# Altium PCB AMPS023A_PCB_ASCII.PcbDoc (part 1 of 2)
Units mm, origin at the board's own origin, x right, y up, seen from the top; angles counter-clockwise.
Board outline 85 x 120 mm, 4 copper layers (Top Layer, Signal Layer 1, Signal Layer 2, Bottom Layer), stack 1.567 mm thick; 131 components, 63 nets, 410 pads, 509 vias.
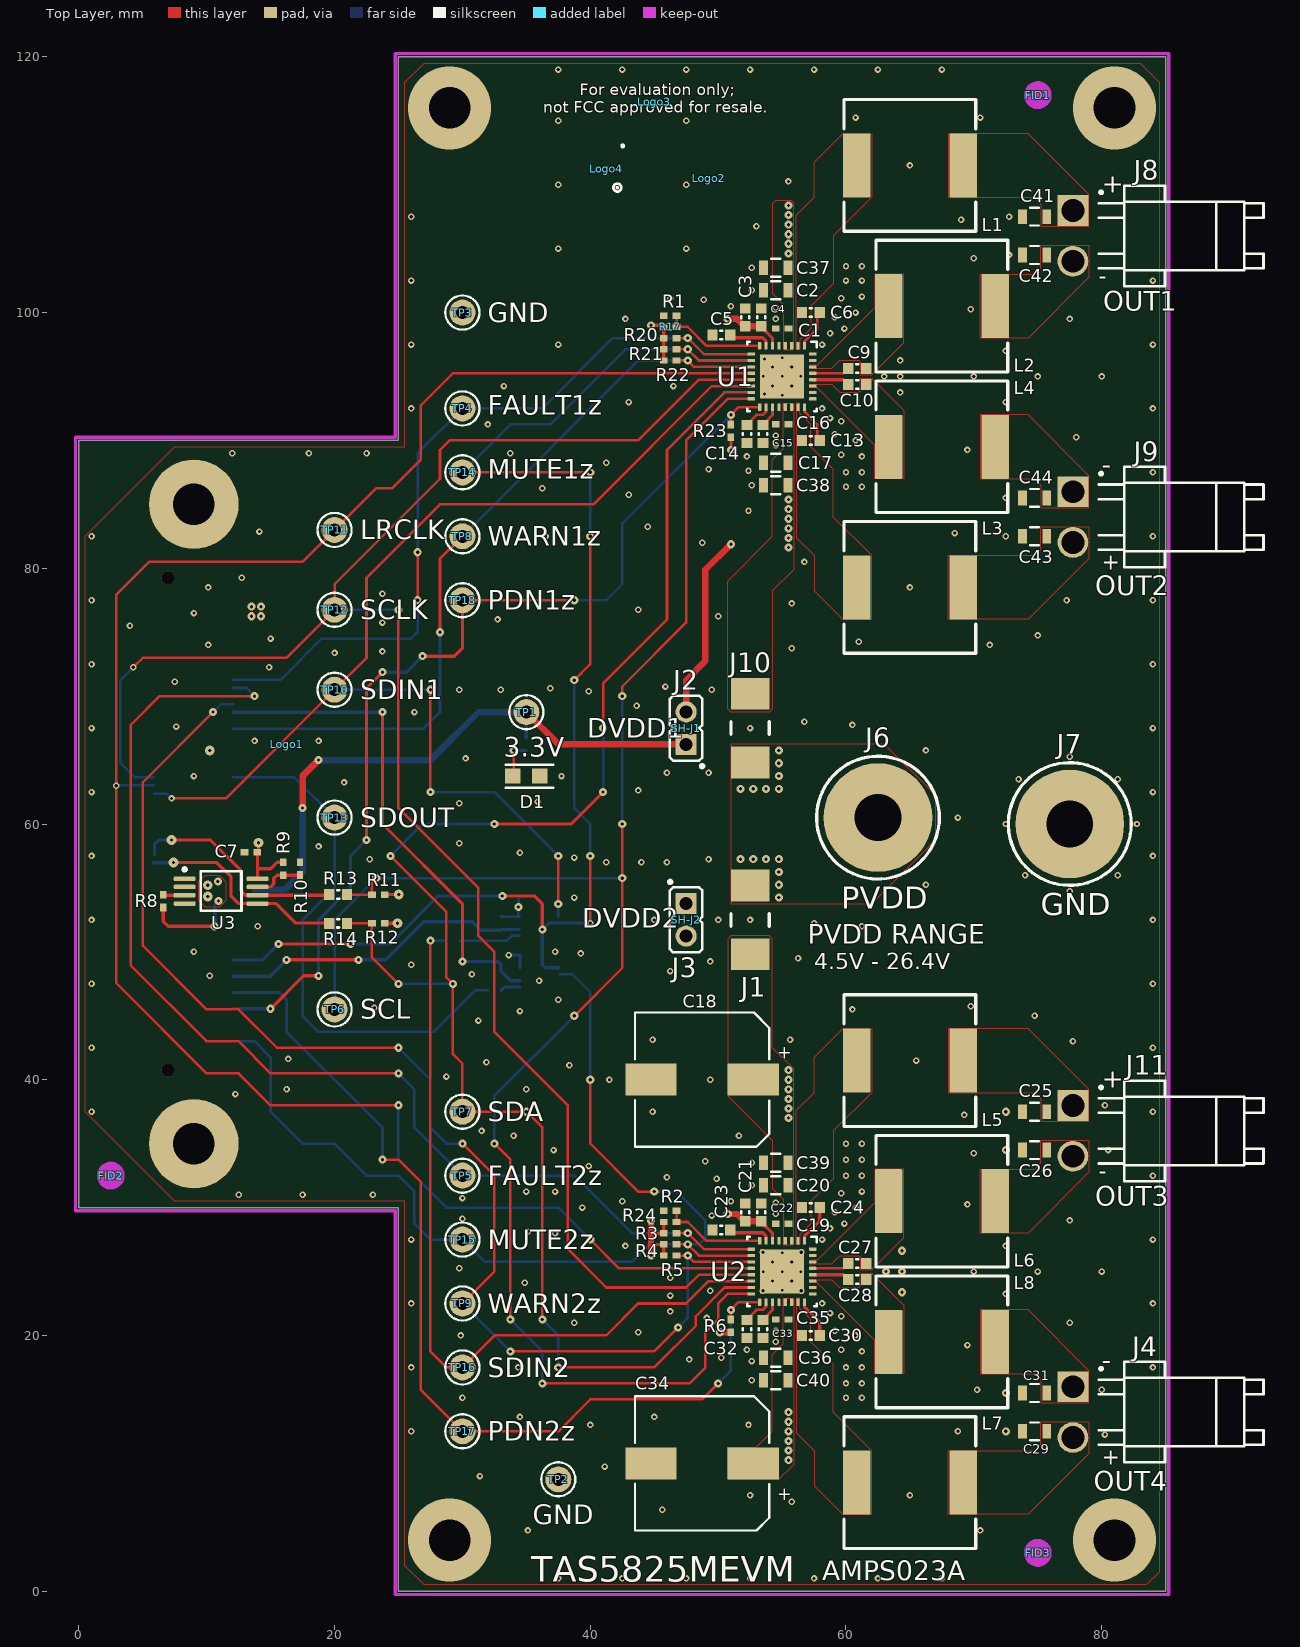
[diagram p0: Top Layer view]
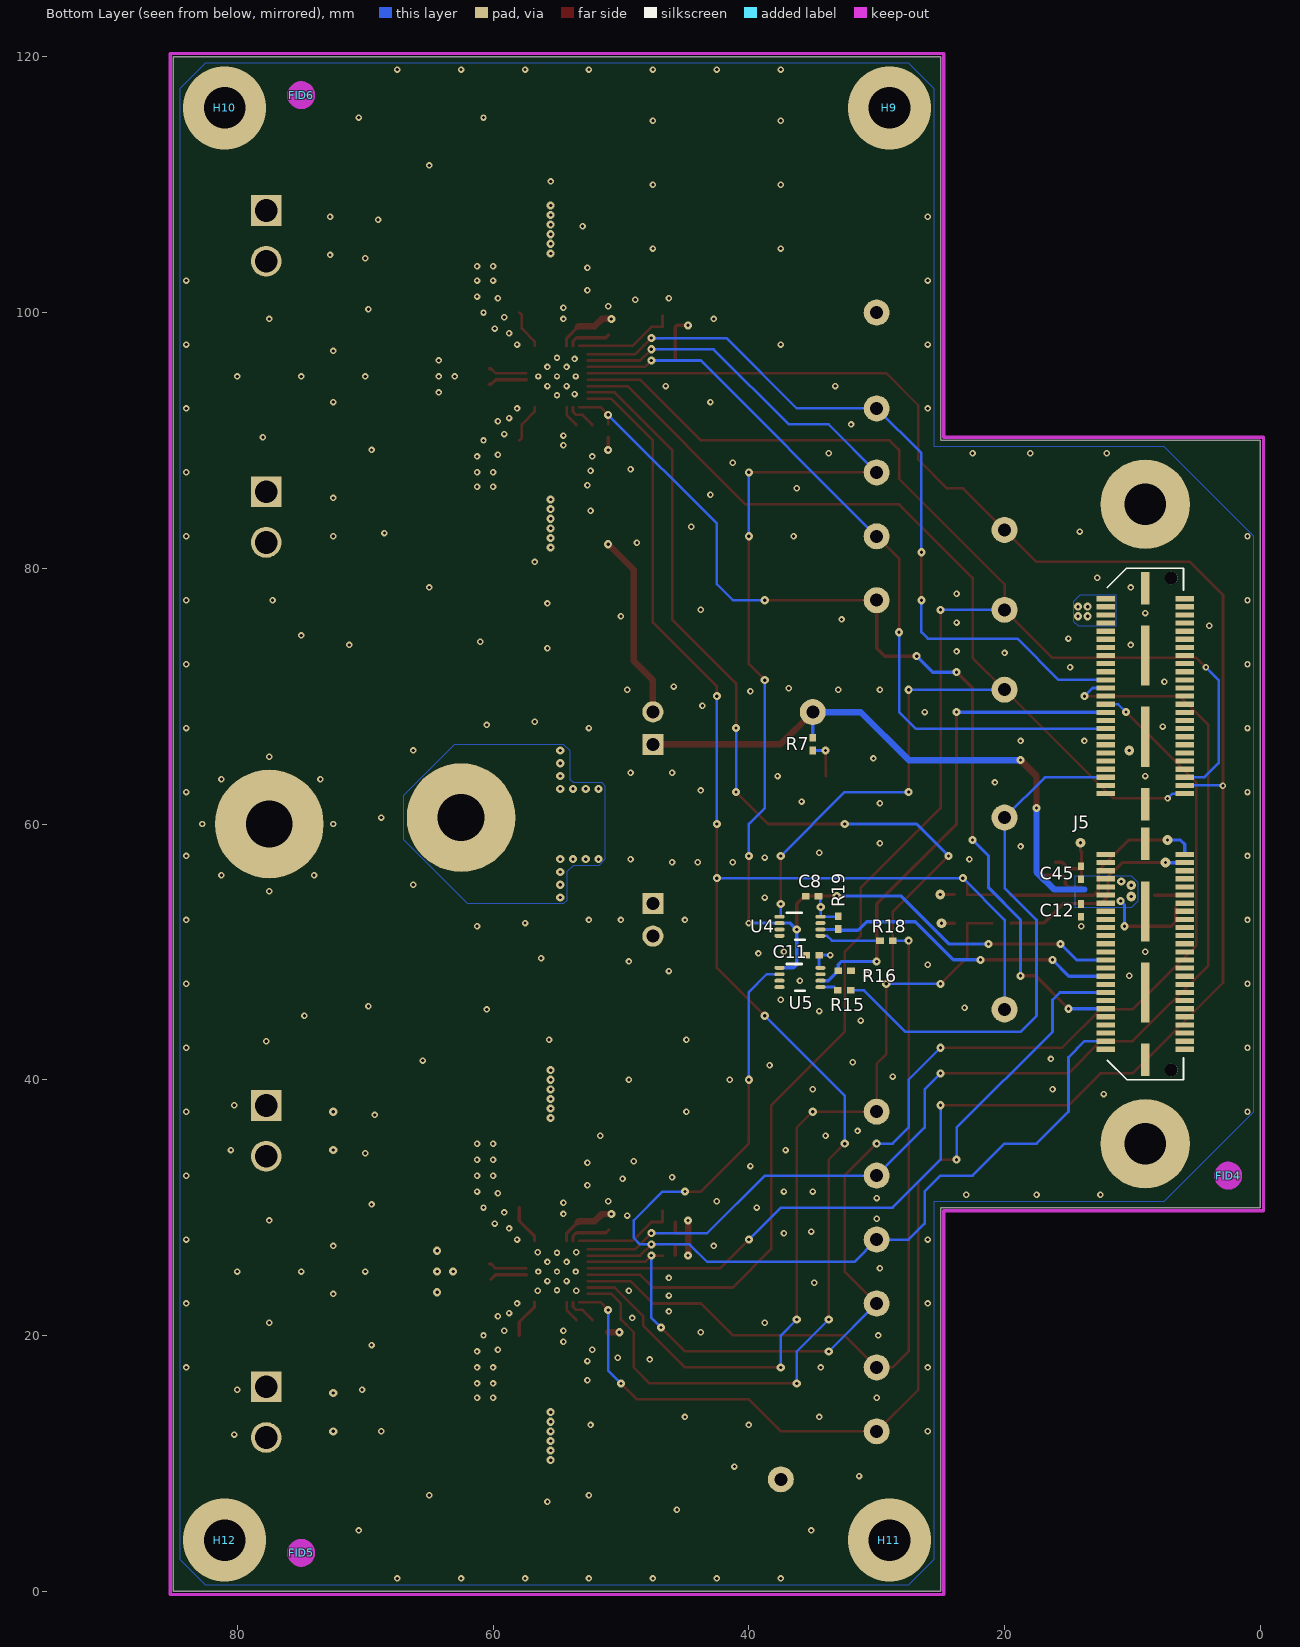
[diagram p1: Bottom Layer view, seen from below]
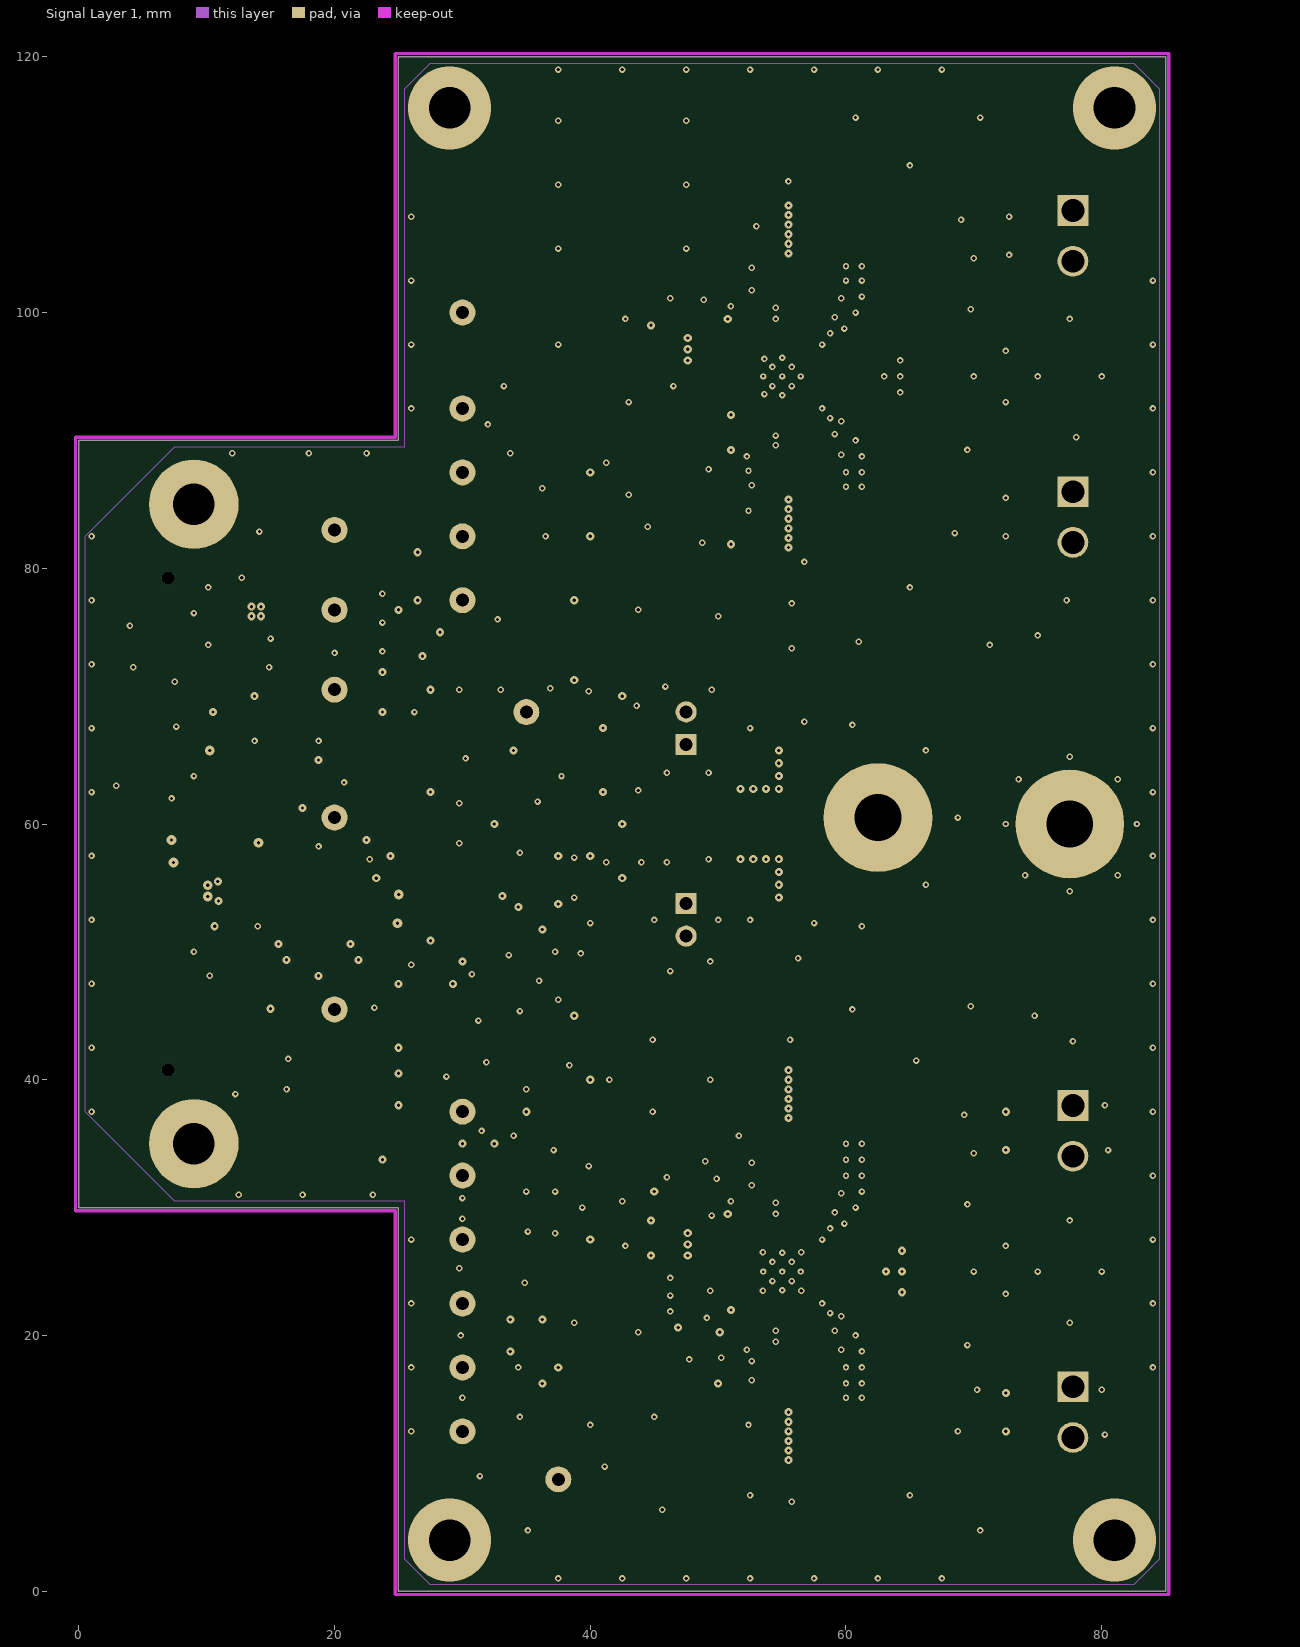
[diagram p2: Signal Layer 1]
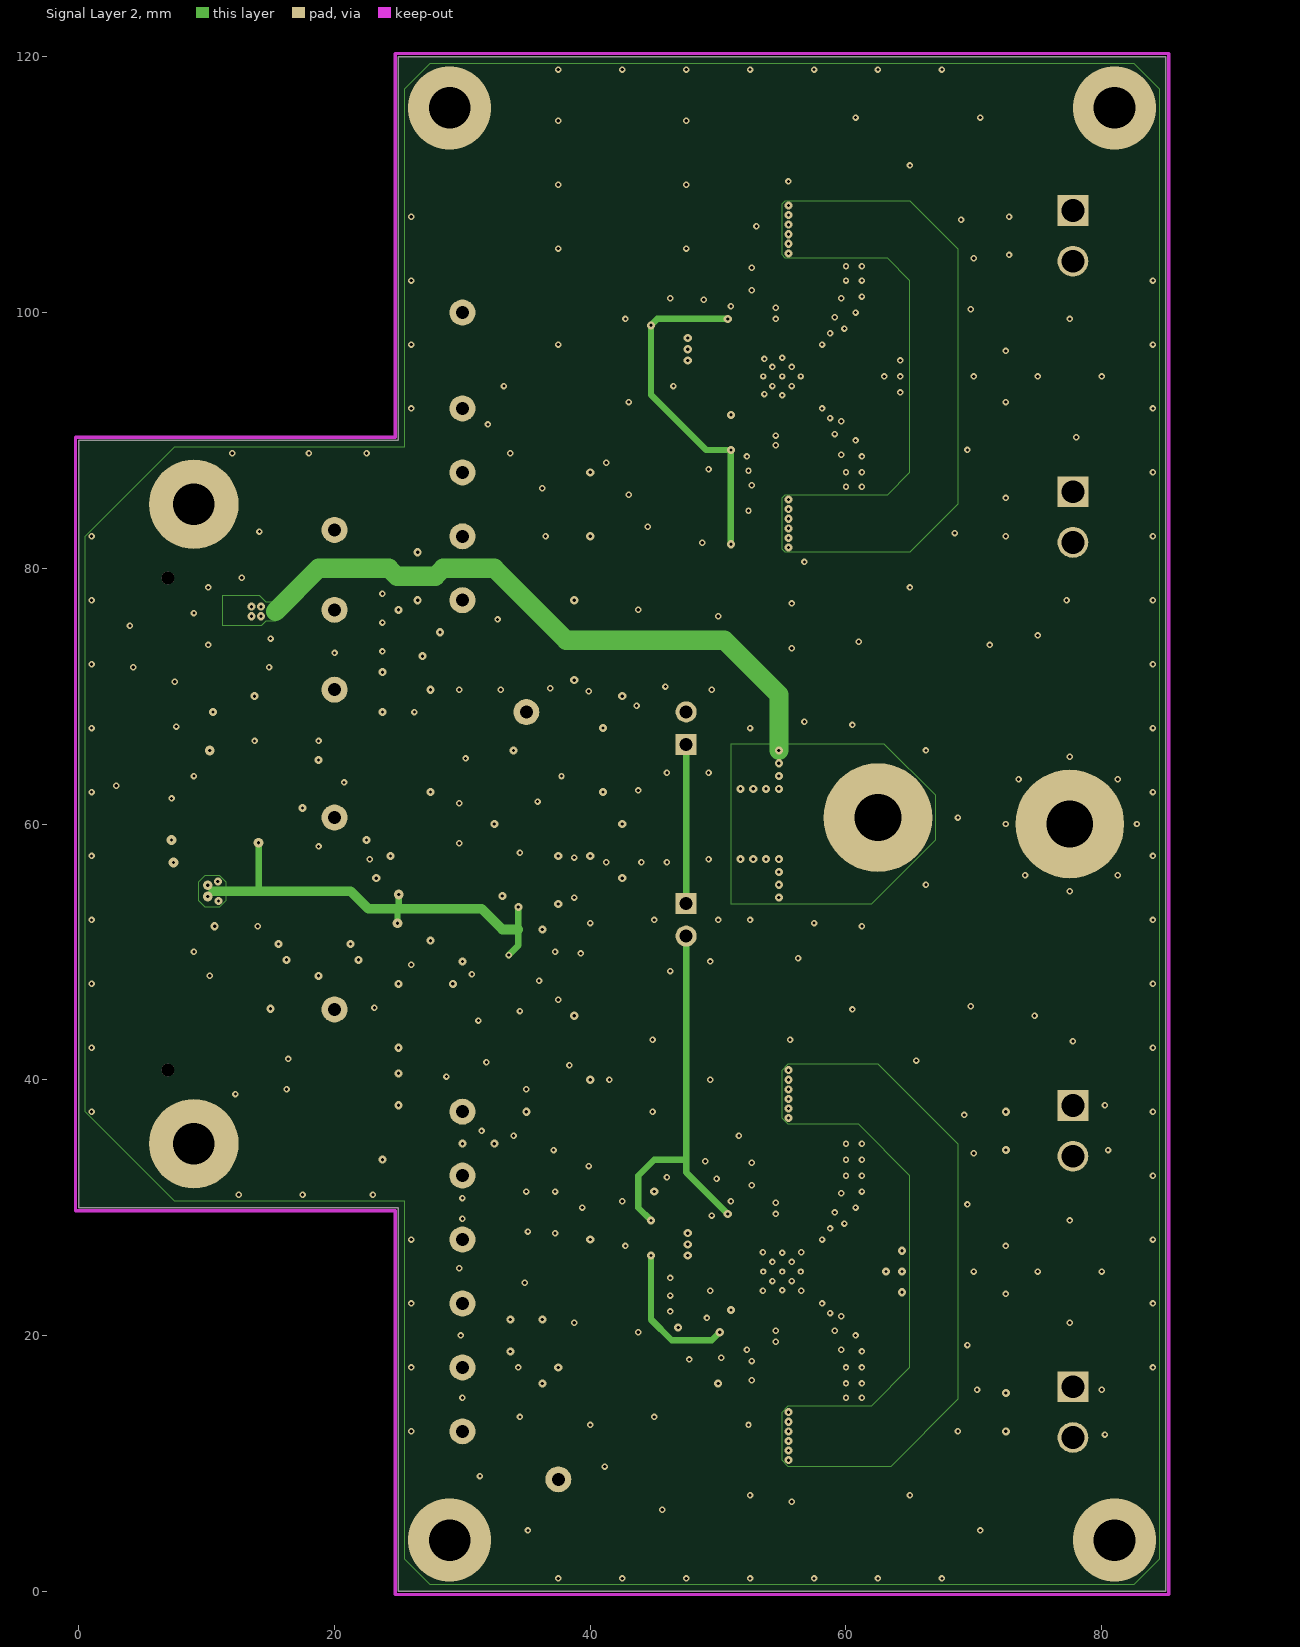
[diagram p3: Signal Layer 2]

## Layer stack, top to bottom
Top Solder: solder mask 0.0102, Solder Resist, Dk 3.5
Top Layer: signal copper 0.0696
Dielectric 1: prepreg 0.2032, FR-4, Dk 4.2
Signal Layer 1: signal copper 0.0356
Dielectric 2: core 0.9505, FR-4, Dk 4.2
Signal Layer 2: signal copper 0.0356
Dielectric 3: prepreg 0.2032, FR-4, Dk 4.2
Bottom Layer: signal copper 0.0696
Bottom Solder: solder mask 0.0102, Solder Resist, Dk 3.5

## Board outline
0,30 25,30 25,0 85,0 85,120 25,120 25,90 0,90

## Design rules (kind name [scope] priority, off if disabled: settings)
AcuteAngle [All] p0: scope1count=1 scope1_0_kind=Board scope1_0_value=Board scope2count=1 scope2_0_kind=Board scope2_0_value=Board commentlength=0 minimum=4.50000000000000E+0001
AcuteAngle [All] p1: minimum=4.50000000000000E+0001 checktracksonly=FALSE
AssemblyTestPointUsage [All] p0: scope1count=1 scope1_0_kind=Board scope1_0_value=Board scope2count=1 scope2_0_kind=Board scope2_0_value=Board commentlength=0
AssemblyTestPointUsage [All] p1: valid=2
AssemblyTestpoint [All] p0: scope1count=1 scope1_0_kind=Board scope1_0_value=Board scope2count=1 scope2_0_kind=Board scope2_0_value=Board commentlength=0
Clearance [All] p0: scope1count=1 scope1_0_kind=Board scope1_0_value=Board scope2count=1 scope2_0_kind=Board scope2_0_value=Board commentlength=0 gap=0.2
Clearance Clearance_Poly [All] p0 off: scope1count=1 scope1_0_kind=Board scope1_0_value=Board scope2count=1 scope2_0_kind=Board scope2_0_value=Board commentlength=48 gap=0.25 // Protel DXP Scope 1 Expression Was: InPolygon
Clearance Clearance_Keepouts [All] p0 off: scope1count=1 scope1_0_kind=Board scope1_0_value=Board scope2count=1 scope2_0_kind=Board scope2_0_value=Board commentlength=99 gap=0 // Protel DXP Scope 2 Expression Was: ((IsTrack Or IsArc) And Not InPoly) And IsFree and IsKeepOut
Clearance "Poly Clearance PVDD" [All] p0: scope1count=1 scope1_0_kind=Board scope1_0_value=Board scope2count=1 scope2_0_kind=Board scope2_0_value=Board commentlength=0 gap=0.2
Clearance "Poly Clearance Outputs" [All] p0 off: scope1count=1 scope1_0_kind=Board scope1_0_value=Board scope2count=1 scope2_0_kind=Board scope2_0_value=Board commentlength=82 gap=0.2 // Protel DXP Scope 2 Expression Was: (InComponent('UD1') AND InComponent('UD2'))
Clearance "Poly Clearance 3.3V" [All] p0 off: scope1count=1 scope1_0_kind=Board scope1_0_value=Board scope2count=1 scope2_0_kind=Board scope2_0_value=Board commentlength=71 gap=0.2 // Protel DXP Scope 1 Expression Was: InNamedPolygon('+3.3V_L04_P006')
Clearance Clearance_BoardEdge_MountingHoles [All] p0 off: scope1count=1 scope1_0_kind=Board scope1_0_value=Board scope2count=1 scope2_0_kind=Board scope2_0_value=Board commentlength=48 gap=0.2 // Protel DXP Scope 2 Expression Was: IsKeepOut
Clearance Clearance_BoardEdge_Poly [All] p0 off: scope1count=1 scope1_0_kind=Board scope1_0_value=Board scope2count=1 scope2_0_kind=Board scope2_0_value=Board commentlength=48 gap=0.2 // Protel DXP Scope 2 Expression Was: IsKeepOut
Clearance Clearance_BoardEdge [All] p0 off: scope1count=1 scope1_0_kind=Board scope1_0_value=Board scope2count=1 scope2_0_kind=Board scope2_0_value=Board commentlength=48 gap=0.2 // Protel DXP Scope 2 Expression Was: IsKeepOut
Clearance "Clearance Fiducial LibErrors" [All] p0: scope1count=1 scope1_0_kind=Component scope1_0_value=FID* scope2count=1 scope2_0_kind=Board scope2_0_value=Board commentlength=0 gap=0.2
Clearance "Clearance Fiducial LibErrors" [InComponent('FID*')] p1: gap=0.2 ignorepadtopadclearanceinfootprint=TRUE except(0: Arc-SMDPad Arc-Hole Track-SMDPad Track-Hole SMDPad-Hole THPad-Hole Via-Hole Fill-Hole Poly-Hole Region-Hole Text-Hole)
Clearance Clearance_BoardEdge [OnCopper and Not InComponentClass('Logo') and not InComponentClass('FiducialMark') and not InRegion(1000,500,4000,800) and Not IsKeepout vs IsKeepOut] p2: gap=0.2 ignorepadtopadclearanceinfootprint=FALSE except(0: Arc-Hole Track-Hole SMDPad-Hole THPad-Hole Via-Hole Fill-Hole Poly-Hole Region-Hole Text-Hole)
Clearance Clearance_BoardEdge_Poly [OnCopper and InPoly vs IsKeepOut] p3: gap=0.2 ignorepadtopadclearanceinfootprint=FALSE except(0: Arc-Hole Track-Hole SMDPad-Hole THPad-Hole Via-Hole Fill-Hole Poly-Hole Region-Hole Text-Hole)
Clearance Clearance_BoardEdge_MountingHoles [OnCopper and InComponentClass('Mounting Hardware') vs IsKeepOut] p4: gap=0.2 ignorepadtopadclearanceinfootprint=FALSE except(0: Arc-Hole Track-Hole SMDPad-Hole THPad-Hole Via-Hole Fill-Hole Poly-Hole Region-Hole Text-Hole)
Clearance "Poly Clearance 3.3V" [InNamedPolygon('+3.3V_L04_P006')] p5: gap=0.2 ignorepadtopadclearanceinfootprint=FALSE except(0: Arc-Hole Track-Hole SMDPad-Hole THPad-Hole Via-Hole Fill-Hole Poly-Hole Region-Hole Text-Hole)
Clearance "Poly Clearance Outputs" [(InNet('SPK1_OUTA+') AND InNet('SPK1_OUTA-') AND InNet('SPK1_OUTB+') AND InNet('SPK1_OUTB-') AND InNet('SPK2_OUTA+') AND InNet('SPK2_OUTA-') AND InNet('SPK2_OUTB+') AND InNet('SPK2_OUTB-')) vs (InComponent('UD1') AND InComponent('UD2'))] p6: gap=0.2 ignorepadtopadclearanceinfootprint=FALSE except(0: Arc-Hole Track-Hole SMDPad-Hole THPad-Hole Via-Hole Fill-Hole Poly-Hole Region-Hole Text-Hole)
Clearance "Poly Clearance PVDD" [All] p7: gap=0.2 ignorepadtopadclearanceinfootprint=FALSE except(0: Arc-Hole Track-Hole SMDPad-Hole THPad-Hole Via-Hole Fill-Hole Poly-Hole Region-Hole Text-Hole)
Clearance Clearance_Keepouts [((IsTrack Or IsArc) And Not InPoly) And IsFree and IsKeepOut vs ((IsTrack Or IsArc) And Not InPoly) And IsFree and IsKeepOut] p8: gap=0 ignorepadtopadclearanceinfootprint=FALSE
Clearance Clearance_Poly [InPolygon] p9: gap=0.25 ignorepadtopadclearanceinfootprint=FALSE except(0: Arc-Hole Track-Hole SMDPad-Hole THPad-Hole Via-Hole Fill-Hole Poly-Hole Region-Hole Text-Hole)
Clearance [All] p10: gap=0.2 ignorepadtopadclearanceinfootprint=FALSE except(0: Arc-Hole Track-Hole SMDPad-Hole THPad-Hole Via-Hole Fill-Hole Poly-Hole Region-Hole Text-Hole)
ComponentClearance "TAS5754 Clearance" [All] p0: scope1count=1 scope1_0_kind=Component scope1_0_value=U2 scope2count=1 scope2_0_kind=Component scope2_0_value=C* commentlength=0 gap=0.251 collisioncheckmode=3
ComponentClearance [All] p0: scope1count=1 scope1_0_kind=Board scope1_0_value=Board scope2count=1 scope2_0_kind=Board scope2_0_value=Board commentlength=0 gap=1.016 collisioncheckmode=3
ComponentClearance ComponentClearance_THtoTH [All] p0 off: scope1count=1 scope1_0_kind=Board scope1_0_value=Board scope2count=1 scope2_0_kind=Board scope2_0_value=Board commentlength=54 gap=0.25 collisioncheckmode=3 // Protel DXP Scope 2 Expression Was: IsThruComponent
ComponentClearance ComponentClearance_THtoSMT [All] p0 off: scope1count=1 scope1_0_kind=Board scope1_0_value=Board scope2count=1 scope2_0_kind=Board scope2_0_value=Board commentlength=53 gap=0 collisioncheckmode=3 // Protel DXP Scope 2 Expression Was: IsSMTComponent
ComponentClearance ComponentClearance_SmallPassives [All] p0 off: scope1count=1 scope1_0_kind=Board scope1_0_value=Board scope2count=1 scope2_0_kind=Board scope2_0_value=Board commentlength=675 gap=0.2 collisioncheckmode=3 // Protel DXP Scope 2 Expression Was: HasFootprint('0201*') or HasFootprint('0402*') or HasFootprint('0508') or HasFootprint('0603*') or HasFootprint('0612') or HasFootprint('0805*') or HasFootprint('0815*') or HasFootprint('0830*') or HasFootprint('1206*') or HasFootprint('1210*') or HasFootprint('1808*') or HasFootprint('1812*') or HasFootprint('1825*') or HasFootprint('2010*') or HasFootprint('2220*') or HasFootprint('2225*') or HasFootprint('2512*') or HasFootprint('2728*') or HasFootprint('3518*') or HasFootprint('DCU*') or HasFootprint('DEM*') or HasFootprint('HAR*') or HasFootprint('IND*') or HasFootprint('NFZ*') or HasFootprint('RHB*') or HasFootprint('SM*')
ComponentClearance ComponentClearance_MountingHoles [All] p0: scope1count=1 scope1_0_kind=ComponentClass scope1_0_value="Mounting Holes" scope2count=1 scope2_0_kind=Board scope2_0_value=Board commentlength=0 gap=6.35 collisioncheckmode=3
ComponentClearance ComponentClearance_ScrewToNut [All] p0 off: scope1count=1 scope1_0_kind=Board scope1_0_value=Board scope2count=1 scope2_0_kind=Board scope2_0_value=Board commentlength=71 gap=0 collisioncheckmode=3 // Protel DXP Scope 2 Expression Was: (HasFootprint('Keystone_1902C'))
ComponentClearance ComponentClearance_Logo [All] p0: scope1count=1 scope1_0_kind=ComponentClass scope1_0_value=Logo scope2count=1 scope2_0_kind=Board scope2_0_value=Board commentlength=0 gap=0 collisioncheckmode=3
ComponentClearance ComponentClearance_Shunt [All] p0: scope1count=1 scope1_0_kind=ComponentClass scope1_0_value=Header scope2count=1 scope2_0_kind=ComponentClass scope2_0_value=Shunt commentlength=0 gap=0 collisioncheckmode=3
ComponentClearance ComponentClearance_MountingHoles_FiducialMarks [All] p0: scope1count=1 scope1_0_kind=ComponentClass scope1_0_value="Mounting Holes" scope2count=1 scope2_0_kind=ComponentClass scope2_0_value=FiducialMark commentlength=0 gap=1.27 collisioncheckmode=3
ComponentClearance "TAS5754 Clearance" [InComponent('U2') vs InComponent('C*')] p1: gap=0.251 collisioncheckmode=3 verticalgap=0 showdistances=FALSE
ComponentClearance ComponentClearance_MountingHoles_FiducialMarks [InComponentClass('Mounting Holes') vs InComponentClass('FiducialMark')] p2: gap=1.27 collisioncheckmode=3 verticalgap=0.254 showdistances=FALSE
ComponentClearance ComponentClearance_Shunt [InComponentClass('Header') vs InComponentClass('Shunt')] p3: gap=0 collisioncheckmode=3 verticalgap=0 showdistances=FALSE
ComponentClearance ComponentClearance_Logo [InComponentClass('Logo')] p4: gap=0 collisioncheckmode=3 verticalgap=0 showdistances=FALSE
ComponentClearance ComponentClearance_ScrewToNut [(HasFootprint('NY PMS 440 0025 PH')) vs (HasFootprint('Keystone_1902C'))] p5: gap=0 collisioncheckmode=3 verticalgap=0 showdistances=FALSE
ComponentClearance ComponentClearance_MountingHoles [InComponentClass('Mounting Holes')] p6: gap=6.35 collisioncheckmode=3 verticalgap=2540 showdistances=FALSE
ComponentClearance ComponentClearance_SmallPassives [HasFootprint('0201*') or HasFootprint('0402*') or HasFootprint('0508') or HasFootprint('0603*') or HasFootprint('0612') or HasFootprint('0805*') or HasFootprint('0815*') or HasFootprint('0830*') or HasFootprint('1206*') or HasFootprint('1210*') or HasFootprint('1808*') or HasFootprint('1812*') or HasFootprint('1825*') or HasFootprint('2010*') or HasFootprint('2220*') or HasFootprint('2225*') or HasFootprint('2512*') or HasFootprint('2728*') or HasFootprint('3518*') or HasFootprint('DCU*') or HasFootprint('DEM*') or HasFootprint('HAR*') or HasFootprint('IND*') or HasFootprint('NFZ*') or HasFootprint('RHB*') or HasFootprint('SM*') vs HasFootprint('0201*') or HasFootprint('0402*') or HasFootprint('0508') or HasFootprint('0603*') or HasFootprint('0612') or HasFootprint('0805*') or HasFootprint('0815*') or HasFootprint('0830*') or HasFootprint('1206*') or HasFootprint('1210*') or HasFootprint('1808*') or HasFootprint('1812*') or HasFootprint('1825*') or HasFootprint('2010*') or HasFootprint('2220*') or HasFootprint('2225*') or HasFootprint('2512*') or HasFootprint('2728*') or HasFootprint('3518*') or HasFootprint('DCU*') or HasFootprint('DEM*') or HasFootprint('HAR*') or HasFootprint('IND*') or HasFootprint('NFZ*') or HasFootprint('RHB*') or HasFootprint('SM*')] p7: gap=0.2 collisioncheckmode=3 verticalgap=0 showdistances=FALSE
ComponentClearance ComponentClearance_THtoSMT [IsThruComponent vs IsSMTComponent] p8: gap=0 collisioncheckmode=3 verticalgap=0 showdistances=FALSE
ComponentClearance ComponentClearance_THtoTH [IsThruComponent vs IsThruComponent] p9: gap=0.25 collisioncheckmode=3 verticalgap=0 showdistances=FALSE
ComponentClearance [All] p10: gap=1.016 collisioncheckmode=3 verticalgap=0.254 showdistances=FALSE
DiffPairsRouting [All] p0: scope1count=1 scope1_0_kind=Board scope1_0_value=Board scope2count=1 scope2_0_kind=Board scope2_0_value=Board commentlength=0
DiffPairsRouting [All] p1: maxlimit=2.54 minlimit=0.254 mostfreqgap=0.254 toplayer_minwidth=0.381 toplayer_maxwidth=0.381 toplayer_prefwidth=0.381 midlayer1_minwidth=0.381 midlayer1_maxwidth=0.381 midlayer1_prefwidth=0.381 midlayer2_minwidth=0.381 midlayer2_maxwidth=0.381 midlayer2_prefwidth=0.381 bottomlayer_minwidth=0.381 bottomlayer_maxwidth=0.381 bottomlayer_prefwidth=0.381 maxuncoupledlength=25.4
FabricationTestPointUsage TestPointUsage [All] p0: scope1count=1 scope1_0_kind=Board scope1_0_value=Board scope2count=1 scope2_0_kind=Board scope2_0_value=Board commentlength=0 valid=2 allowmultiple=FALSE
FabricationTestPointUsage TestPointUsage [All] p1: valid=2 allowmultiple=FALSE
FabricationTestpoint Testpoint [All] p0: scope1count=1 scope1_0_kind=Board scope1_0_value=Board scope2count=1 scope2_0_kind=Board scope2_0_value=Board commentlength=0 side=3 testpointundercomponent=TRUE minsize=1.016 maxsize=2.54 preferedsize=1.524 minholesize=0 maxholesize=1.016 preferedholesize=0.813 testpointgrid=0.025
FabricationTestpoint Testpoint [All] p1: side=3 testpointundercomponent=TRUE minsize=1.016 maxsize=2.54 preferedsize=1.524 minholesize=0 maxholesize=1.016 preferedholesize=0.813 testpointgrid=0.025 allowsidetop=TRUE allowsidebottom=TRUE usegrid=TRUE gridtolerance=0
FanoutControl Fanout_Small [All] p0 off: scope1count=1 scope1_0_kind=Board scope1_0_value=Board scope2count=1 scope2_0_kind=Board scope2_0_value=Board commentlength=84 // Protel DXP Scope 1 Expression Was: (CompPinCount < 5)   Fanout_Small (Default Rule)
FanoutControl Fanout_Default [All] p0: scope1count=1 scope1_0_kind=Board scope1_0_value=Board scope2count=1 scope2_0_kind=Board scope2_0_value=Board commentlength=30 // Fanout_Default (Default Rule)
FanoutControl Fanout_SOIC [All] p0 off: scope1count=1 scope1_0_kind=Board scope1_0_value=Board scope2count=1 scope2_0_kind=Board scope2_0_value=Board commentlength=71 // Protel DXP Scope 1 Expression Was: IsSOIC   Fanout_SOIC (Default Rule)
FanoutControl Fanout_BGA [All] p0 off: scope1count=1 scope1_0_kind=Board scope1_0_value=Board scope2count=1 scope2_0_kind=Board scope2_0_value=Board commentlength=69 // Protel DXP Scope 1 Expression Was: IsBGA   Fanout_BGA (Default Rule)
FanoutControl Fanout_LCC [All] p0 off: scope1count=1 scope1_0_kind=Board scope1_0_value=Board scope2count=1 scope2_0_kind=Board scope2_0_value=Board commentlength=69 // Protel DXP Scope 1 Expression Was: IsLCC   Fanout_LCC (Default Rule)
FanoutControl Fanout_LCC [IsLCC] p1: bgadir=Out bgaviamode=Centered fanoutstyle=Auto fanoutdirection=Alternating viagrid=0.025 // Fanout_LCC (Default Rule)
FanoutControl Fanout_BGA [IsBGA] p2: bgadir=Out bgaviamode=Centered fanoutstyle=Auto fanoutdirection=Alternating viagrid=0.025 // Fanout_BGA (Default Rule)
FanoutControl Fanout_Default [All] p4: bgadir=Out bgaviamode=Centered fanoutstyle=Auto fanoutdirection=Alternating viagrid=0.025 // Fanout_Default (Default Rule)
FanoutControl Fanout_Small [(CompPinCount < 5)] p5: bgadir=Out bgaviamode=Centered fanoutstyle=Auto fanoutdirection=OutThenIn viagrid=0.025 // Fanout_Small (Default Rule)
Height [All] p0: scope1count=1 scope1_0_kind=Board scope1_0_value=Board scope2count=1 scope2_0_kind=Board scope2_0_value=Board commentlength=0
Height [All] p1: minheight=0 maxheight=40 prefheight=25
HoleSize [All] p0: scope1count=1 scope1_0_kind=Board scope1_0_value=Board scope2count=1 scope2_0_kind=Board scope2_0_value=Board commentlength=0 absolutevalues=TRUE maxlimit=3.81 minlimit=0.191 maxpercent=80.000 minpercent=20.000
HoleSize [All] p1: absolutevalues=TRUE maxlimit=3.81 minlimit=0.191 maxpercent=80.000 minpercent=20.000
HoleToHoleClearance [All] p0: scope1count=1 scope1_0_kind=Board scope1_0_value=Board scope2count=1 scope2_0_kind=Board scope2_0_value=Board commentlength=0
HoleToHoleClearance "Hole 2 Hole For Hardware" [All] p0 off: scope1count=1 scope1_0_kind=Board scope1_0_value=Board scope2count=1 scope2_0_kind=Board scope2_0_value=Board commentlength=128 // Protel DXP Scope 2 Expression Was: (InComponentClass('Screw') OR InComponentClass('Standoff') OR InComponentClass('Washer'))
HoleToHoleClearance "Hole 2 Hole For Hardware" [(InComponentClass('Screw') OR InComponentClass('Standoff') OR InComponentClass('Washer')) vs (InComponentClass('Screw') OR InComponentClass('Standoff') OR InComponentClass('Washer'))] p1: gap=0 allowstackedmicrovias=TRUE
HoleToHoleClearance [All] p2: gap=0.254 allowstackedmicrovias=TRUE
LayerPairs [All] p0: scope1count=1 scope1_0_kind=Board scope1_0_value=Board scope2count=1 scope2_0_kind=Board scope2_0_value=Board commentlength=0 enforce=TRUE
MinimumAnnularRing [All] p0: scope1count=1 scope1_0_kind=Board scope1_0_value=Board scope2count=1 scope2_0_kind=Board scope2_0_value=Board commentlength=0 minimumring=0.127
MinimumAnnularRing MinimumAnnularRing_ThermalPadVias [All] p0 off: scope1count=1 scope1_0_kind=Board scope1_0_value=Board scope2count=1 scope2_0_kind=Board scope2_0_value=Board commentlength=63 minimumring=0.15 // Protel DXP Scope 1 Expression Was: IsVia and InAnyComponent
MinimumAnnularRing MinimumAnnularRing_ThermalPadVias [IsVia and InAnyComponent] p1: minimumring=0.15
MinimumAnnularRing [All] p2: minimumring=0.127
MinimumSolderMaskSliver [All] p0: scope1count=1 scope1_0_kind=Board scope1_0_value=Board scope2count=1 scope2_0_kind=Board scope2_0_value=Board commentlength=0
MinimumSolderMaskSliver MinimumSolderMaskSliver_Logo [All] p0: scope1count=1 scope1_0_kind=ComponentClass scope1_0_value=Logo scope2count=1 scope2_0_kind=ComponentClass scope2_0_value=Logo commentlength=0
MinimumSolderMaskSliver "MinSolderMaskSliver LibErrors" [All] p0 off: scope1count=1 scope1_0_kind=Board scope1_0_value=Board scope2count=1 scope2_0_kind=Board scope2_0_value=Board commentlength=83 // Protel DXP Scope 1 Expression Was: (HasFootprint('DB*') or HasFootprint('DC*'))
MinimumSolderMaskSliver "MinSolderMaskSliver LibErrors" [(HasFootprint('DB*') or HasFootprint('DC*'))] p1: minsoldermaskwidth=0.089
MinimumSolderMaskSliver MinimumSolderMaskSliver_Logo [InComponentClass('Logo') vs InComponentClass('Logo')] p2: minsoldermaskwidth=0.018
MinimumSolderMaskSliver [All] p3: minsoldermaskwidth=0.127
NetAntennae [All] p0: scope1count=1 scope1_0_kind=Board scope1_0_value=Board scope2count=1 scope2_0_kind=Board scope2_0_value=Board commentlength=0
PasteMaskExpansion [All] p0: scope1count=1 scope1_0_kind=Board scope1_0_value=Board scope2count=1 scope2_0_kind=Board scope2_0_value=Board commentlength=0 expansion=0
PlaneClearance [All] p0: scope1count=1 scope1_0_kind=Board scope1_0_value=Board scope2count=1 scope2_0_kind=Board scope2_0_value=Board commentlength=0 clearance=0.508
PlaneConnect [All] p0: scope1count=1 scope1_0_kind=Board scope1_0_value=Board scope2count=1 scope2_0_kind=Board scope2_0_value=Board commentlength=0 planeconnectstyle=Relief reliefexpansion=0.254 reliefentries=4 reliefconductorwidth=0.254 reliefairgap=0.254
PlaneConnect [All] p1: planeconnectstyle=Relief reliefexpansion=0.254 reliefentries=4 reliefconductorwidth=0.254 reliefairgap=0.254
PolygonConnect [All] p0: scope1count=1 scope1_0_kind=Board scope1_0_value=Board scope2count=1 scope2_0_kind=Board scope2_0_value=Board commentlength=0 connectstyle=Relief reliefconductorwidth=0.25 reliefentries=4 polygonreliefangle="90 Angle"
PolygonConnect "PostFlood GND" [All] p0 off: scope1count=1 scope1_0_kind=Board scope1_0_value=Board scope2count=1 scope2_0_kind=Net scope2_0_value=GND commentlength=184 connectstyle=Direct reliefconductorwidth=0.254 reliefentries=4 polygonreliefangle="90 Angle" // Protel DXP Scope 1 Expression Was: (InComponent('C*') OR InComponent('J2') OR InComponent('J6') OR InComponent('J7') OR InComponent('J8') OR InComponent('U1') OR InComponent('U2'))
PolygonConnect "Wide Thermals" [All] p0 off: scope1count=1 scope1_0_kind=Board scope1_0_value=Board scope2count=1 scope2_0_kind=Net scope2_0_value=GND commentlength=144 connectstyle=Relief reliefconductorwidth=0.25 reliefentries=4 polygonreliefangle="90 Angle" // Protel DXP Scope 1 Expression Was: (InComponent('C1') OR InComponent('C3') OR InComponent('C5') OR InComponent('C6') OR InComponent('C137'))
PolygonConnect "Narrow Thermals" [All] p0 off: scope1count=1 scope1_0_kind=Board scope1_0_value=Board scope2count=1 scope2_0_kind=Net scope2_0_value=GND commentlength=185 connectstyle=Relief reliefconductorwidth=0.2 reliefentries=4 polygonreliefangle="90 Angle" // Protel DXP Scope 1 Expression Was: (InComponent('C*') OR InComponent('D*') OR InComponent('J*') OR InComponent('R*') OR InComponent('S*') OR InComponent('TP*') OR InComponent('U*'))
PolygonConnect PreFlood [All] p0: scope1count=1 scope1_0_kind=Board scope1_0_value=Board scope2count=1 scope2_0_kind=Board scope2_0_value=Board commentlength=0 connectstyle=Direct reliefconductorwidth=0.254 reliefentries=4 polygonreliefangle="90 Angle"
PolygonConnect PreFlood [All] p1: connectstyle=Direct reliefconductorwidth=0.254 reliefentries=4 polygonreliefangle="90 Angle" airgapwidth=0.254
PolygonConnect "Narrow Thermals" [(InComponent('C*') OR InComponent('D*') OR InComponent('J*') OR InComponent('R*') OR InComponent('S*') OR InComponent('TP*') OR InComponent('U*')) vs InNet('GND')] p2: connectstyle=Relief reliefconductorwidth=0.2 reliefentries=4 polygonreliefangle="90 Angle" airgapwidth=0.2
PolygonConnect "Wide Thermals" [(InComponent('C1') OR InComponent('C3') OR InComponent('C5') OR InComponent('C6') OR InComponent('C137')) vs InNet('GND')] p3: connectstyle=Relief reliefconductorwidth=0.25 reliefentries=4 polygonreliefangle="90 Angle" airgapwidth=1
PolygonConnect "PostFlood GND" [(InComponent('C*') OR InComponent('J2') OR InComponent('J6') OR InComponent('J7') OR InComponent('J8') OR InComponent('U1') OR InComponent('U2')) vs InNet('GND')] p4: connectstyle=Direct reliefconductorwidth=0.254 reliefentries=4 polygonreliefangle="90 Angle" airgapwidth=0.254
PolygonConnect [All] p5: connectstyle=Relief reliefconductorwidth=0.25 reliefentries=4 polygonreliefangle="90 Angle" airgapwidth=0.75
RoutingCorners [All] p0: scope1count=1 scope1_0_kind=Board scope1_0_value=Board scope2count=1 scope2_0_kind=Board scope2_0_value=Board commentlength=0 cornerstyle=45-Degree minsetback=2.54 maxsetback=2.54
RoutingLayers [All] p0: scope1count=1 scope1_0_kind=Board scope1_0_value=Board scope2count=1 scope2_0_kind=Board scope2_0_value=Board commentlength=0 top layer=Automatic mid layer 1=Automatic mid layer 2=Automatic bottom layer=Automatic
RoutingPriority [All] p0: scope1count=1 scope1_0_kind=Board scope1_0_value=Board scope2count=1 scope2_0_kind=Board scope2_0_value=Board commentlength=0
RoutingTopology [All] p0: scope1count=1 scope1_0_kind=Board scope1_0_value=Board scope2count=1 scope2_0_kind=Board scope2_0_value=Board commentlength=0 topology=Shortest
RoutingVias [All] p0: scope1count=1 scope1_0_kind=Board scope1_0_value=Board scope2count=1 scope2_0_kind=Board scope2_0_value=Board commentlength=0 holewidth=0.203 width=0.711 viastyle="Through Hole" minholewidth=0.203 minwidth=0.457 maxholewidth=3.25 maxwidth=7
RoutingVias ThermalPadVias [All] p0 off: scope1count=1 scope1_0_kind=Board scope1_0_value=Board scope2count=1 scope2_0_kind=Board scope2_0_value=Board commentlength=63 holewidth=0.2 width=0.5 viastyle="Through Hole" minholewidth=0.2 minwidth=0.5 maxholewidth=0.33 maxwidth=0.6 // Protel DXP Scope 1 Expression Was: IsVia and InAnyComponent
RoutingVias ThermalPadVias [IsVia and InAnyComponent] p1: holewidth=0.2 width=0.5 viastyle="Through Hole" minholewidth=0.2 minwidth=0.5 maxholewidth=0.33 maxwidth=0.6
RoutingVias [All] p2: holewidth=0.203 width=0.711 viastyle="Through Hole" minholewidth=0.203 minwidth=0.457 maxholewidth=3.25 maxwidth=7
ShortCircuit [All] p0: scope1count=1 scope1_0_kind=Board scope1_0_value=Board scope2count=1 scope2_0_kind=Board scope2_0_value=Board commentlength=0 allowed=FALSE
SilkToBoardRegionClearance [All] p0 off: scope1count=1 scope1_0_kind=Board scope1_0_value=Board scope2count=1 scope2_0_kind=Board scope2_0_value=Board commentlength=130 // Protel DXP Scope 1 Expression Was: Not ((IsComment or IsDesignator) And (Hide <> 'False')) and not InRegion(1000,500,4000,800)
SilkToBoardRegionClearance [Not ((IsComment or IsDesignator) And (Hide <> 'False')) and not InRegion(1000,500,4000,800)] p1:
SilkToSilkClearance [All] p0: scope1count=1 scope1_0_kind=Board scope1_0_value=Board scope2count=1 scope2_0_kind=Board scope2_0_value=Board commentlength=0
SilkToSilkClearance SilkToSilkClearance_Pb-FreeLogo [All] p0 off: scope1count=1 scope1_0_kind=Board scope1_0_value=Board scope2count=1 scope2_0_kind=Board scope2_0_value=Board commentlength=120 // Protel DXP Scope 2 Expression Was: (HasFootprint('Pb-Free_Overlay_Medium') OR HasFootprint('Pb-Free_Overlay_Small'))
SilkToSilkClearance SilkToSilkClearance_Pb-FreeLogo [(HasFootprint('Pb-Free_Overlay_Medium') OR HasFootprint('Pb-Free_Overlay_Small')) vs (HasFootprint('Pb-Free_Overlay_Medium') OR HasFootprint('Pb-Free_Overlay_Small'))] p1: silktosilkclearance=0
SilkToSilkClearance [All] p2: silktosilkclearance=0.127
SilkToSolderMaskClearance "SilkToMask LibErrors" [All] p0 off: scope1count=1 scope1_0_kind=Board scope1_0_value=Board scope2count=1 scope2_0_kind=Board scope2_0_value=Board commentlength=84 // Protel DXP Scope 1 Expression Was: HasFootprint('LTST*') or HasFootprint('DCU*')
SilkToSolderMaskClearance "Silk to Solder Mask Opening" [All] p0: scope1count=1 scope1_0_kind=Board scope1_0_value=Board scope2count=1 scope2_0_kind=Board scope2_0_value=Board commentlength=0
SilkToSolderMaskClearance SilkToComponentPadClearance [All] p0 off: scope1count=1 scope1_0_kind=Board scope1_0_value=Board scope2count=1 scope2_0_kind=Board scope2_0_value=Board commentlength=87 // Protel DXP Scope 1 Expression Was: (IsPad or IsFill or IsRegion) and InAnycomponent
SilkToSolderMaskClearance "SilkToMask LibErrors" [HasFootprint('LTST*') or HasFootprint('DCU*')] p1: minsilkscreentomaskgap=0.076 clearancetoexposedcopper=FALSE
SilkToSolderMaskClearance SilkToComponentPadClearance [(IsPad or IsFill or IsRegion) and InAnycomponent] p2: minsilkscreentomaskgap=0.127 clearancetoexposedcopper=TRUE
SilkToSolderMaskClearance "Silk to Solder Mask Opening" [All] p3: minsilkscreentomaskgap=0.019 clearancetoexposedcopper=FALSE
SolderMaskExpansion [All] p0: scope1count=1 scope1_0_kind=Board scope1_0_value=Board scope2count=1 scope2_0_kind=Board scope2_0_value=Board commentlength=0 expansion=0.05
SolderMaskExpansion [All] p1: expansion=0.05
UnRoutedNet [All] p0: scope1count=1 scope1_0_kind=Board scope1_0_value=Board scope2count=1 scope2_0_kind=Board scope2_0_value=Board commentlength=0
UnpouredPolygon [All] p0: scope1count=1 scope1_0_kind=Board scope1_0_value=Board scope2count=1 scope2_0_kind=Board scope2_0_value=Board commentlength=0
Width [All] p0: scope1count=1 scope1_0_kind=Board scope1_0_value=Board scope2count=1 scope2_0_kind=Board scope2_0_value=Board commentlength=0 maxlimit=5 minlimit=0.15 preferedwidth=0.25
Width [All] p1: maxlimit=5 minlimit=0.15 preferedwidth=0.25 checkconnectedcopper=TRUE
13 further rules are at their usual default settings.

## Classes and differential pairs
component class Shunt: SH-J1 SH-J2
component class Header: J2 J3
component class AMPS023A_PPCMB-IO: C7 C8 C11 C12 C45 D1 J1 J2 J3 J5 J6 J7 J10 R7 R8 R9 R10 R11 R12 R13 R14 R15 R16 R18 R19 R25 R26 R33 R35 R38 R39 R40 TP1 TP2 TP3 TP4 TP5 TP6 TP7 TP8 TP9 TP10 TP11 TP12 TP13 TP14 TP15 TP16 TP17 TP18 U3 U4 U5
component class AMPS023A_BTL2: C18 C19 C20 C21 C22 C23 C24 C25 C26 C27 C28 C29 C30 C31 C32 C33 C34 C35 C36 C39 C40 J4 J11 L5 L6 L7 L8 R2 R3 R4 R5 R6 R24 U2
component class AMPS023A_BTL1: C1 C2 C3 C4 C5 C6 C9 C10 C13 C14 C15 C16 C17 C37 C38 C41 C42 C43 C44 J8 J9 L1 L2 L3 L4 R1 R17 R20 R21 R22 R23 U1
component class Logo: Logo1
component class AMPS023A_EVM_Hardware: FID1 FID2 FID3 FID4 FID5 FID6 H9 H10 H11 H12 Logo1 Logo2 Logo3 Logo4 SH-J1 SH-J2 ZZ1 ZZ2 ZZ3
component class FiducialMark: FID1 FID2 FID3 FID4 FID5 FID6
component class AssemblyNote: ZZ1 ZZ2 ZZ3

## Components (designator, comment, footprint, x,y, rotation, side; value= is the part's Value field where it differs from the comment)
C1 "C1005X7R1H104K050BB" 0402L 55,98.75 r180 top
C2 "C2012JB1V226M125AC" 0805_KTR 54.5,101.75 r0 top
C3 "C0603C475K8PACTU" 0603L 52.125,99.625 r270 top
C4 "C0603C104K4RACTU" 0603L 53.375,99.625 r90 top
C5 "C0603C105K4PACTU" 0603L 50.25,98.25 r180 top
C6 "C1608X7R1H224K080AB" 0603L 57.25,100 r180 top
C7 "C1005X7R1H104K050BB" 0402L 13.462,57.784 r180 top
C8 "C1005X7R1H104K050BB" 0402L 35.052,54.356 r180 bottom
C9 "C1608X7R1H224K080AB" 0603L 60.875,95.625 r0 top
C10 "C1608X7R1H224K080AB" 0603L 60.875,94.375 r0 top
C11 "C1005X7R1H104K050BB" 0402L 35,49.75 r180 bottom
C12 "C1005X7R1H104K050BB" 0402L 14.021,53.237 r90 bottom
C13 "C1608X7R1H224K080AB" 0603L 57.25,90 r180 top
C14 "C0603C105K4PACTU" 0603L 52.25,90.5 r270 top
C15 "C0603C105K4PACTU" 0603L 53.5,90.5 r270 top
C16 "C1005X7R1H104K050BB" 0402L 55,91.25 r180 top
C17 "C2012JB1V226M125AC" 0805_KTR 54.5,88.25 r0 top
C18 "+" SM_RADIAL_10BMM 48.75,40 r180 top
C19 "C1005X7R1H104K050BB" 0402L 55,28.75 r180 top
C20 "C2012JB1V226M125AC" 0805_KTR 54.5,31.75 r0 top
C21 "C0603C475K8PACTU" 0603L 52.125,29.625 r270 top
C22 "C0603C104K4RACTU" 0603L 53.375,29.625 r90 top
C23 "C0603C105K4PACTU" 0603L 50.25,28.25 r180 top
C24 "C1608X7R1H224K080AB" 0603L 57.25,30 r180 top
C25 "C0805C684K5RACTU" 0805_KTR 74.75,37.5 r180 top
C26 "C0805C684K5RACTU" 0805_KTR 74.75,34.5 r180 top
C27 "C1608X7R1H224K080AB" 0603L 60.875,25.625 r0 top
C28 "C1608X7R1H224K080AB" 0603L 60.875,24.375 r0 top
C29 "C0805C684K5RACTU" 0805_KTR 74.75,12.5 r180 top
C30 "C1608X7R1H224K080AB" 0603L 57.25,20 r180 top
C31 "C0805C684K5RACTU" 0805_KTR 74.75,15.5 r180 top
C32 "C0603C105K4PACTU" 0603L 52.25,20.5 r270 top
C33 "C0603C105K4PACTU" 0603L 53.5,20.5 r270 top
C34 "+" SM_RADIAL_10BMM 48.75,10 r180 top
C35 "C1005X7R1H104K050BB" 0402L 55,21.25 r180 top
C36 "C2012JB1V226M125AC" 0805_KTR 54.5,18.25 r0 top
C37 "C2012JB1V226M125AC" 0805_KTR 54.5,103.5 r0 top
C38 "C2012JB1V226M125AC" 0805_KTR 54.5,86.5 r0 top
C39 "C2012JB1V226M125AC" 0805_KTR 54.5,33.5 r0 top
C40 "C2012JB1V226M125AC" 0805_KTR 54.5,16.5 r0 top
C41 "C0805C684K5RACTU" 0805_KTR 74.75,107.5 r180 top
C42 "C0805C684K5RACTU" 0805_KTR 74.75,104.5 r180 top
C43 "C0805C684K5RACTU" 0805_KTR 74.75,82.5 r180 top
C44 "C0805C684K5RACTU" 0805_KTR 74.75,85.5 r180 top
C45 "C1005X7R1H104K050BB" 0402L 14.021,56.184 r270 bottom
D1 "3.3V" LTST-C170KGKT_Green 35,63.75 r0 top
FID1 "DNP" Fiducial6.4-20 75,117 r0 top
FID2 "DNP" Fiducial6.4-20 2.5,32.5 r0 top
FID3 "DNP" Fiducial6.4-20 75,3 r0 top
FID4 "DNP" Fiducial6.4-20 2.5,32.5 r180 bottom
FID5 "DNP" Fiducial6.4-20 75,3 r180 bottom
FID6 "DNP" Fiducial6.4-20 75,117 r180 bottom
H9 "Standoff, M3x30mm" Harwin_R30-1003002 29,116 r180 bottom
H10 "Standoff, M3x30mm" Harwin_R30-1003002 81,116 r180 bottom
H11 "Standoff, M3x30mm" Harwin_R30-1003002 29,4 r180 bottom
H12 "Standoff, M3x30mm" Harwin_R30-1003002 81,4 r180 bottom
J1 "" HARWIN_S1911-46R 52.5,52.5 r90 top
J2 "DVDD1" Sullins_PBC02SAAN 47.5,67.5 r180 top
J3 "DVDD2" Sullins_PBC02SAAN 47.5,52.5 r0 top
J4 "OUT4" JST_B2PS-VH 77.75,14 r0 top
J5 "QTS-050-01-F-D-A" CONN_QTS-050-01-F-D-A 9,60 r270 bottom locked
J6 "PVDD" Keystone_7006 62.5,60.5 r0 top locked
J7 "GND" Keystone_7007 77.5,60 r0 top
J8 "OUT1" JST_B2PS-VH 77.75,106 r0 top
J9 "OUT2" JST_B2PS-VH 77.75,84 r0 top
J10 "" HARWIN_S1911-46R 52.5,67.5 r270 top
J11 "OUT3" JST_B2PS-VH 77.75,36 r0 top
L1 "1274AS-H-100M=P3" DEM10050C 65,111.5 r0 top
L2 "1274AS-H-100M=P3" DEM10050C 67.5,100.5 r0 top
L3 "1274AS-H-100M=P3" DEM10050C 65,78.5 r0 top
L4 "1274AS-H-100M=P3" DEM10050C 67.5,89.5 r0 top
L5 "1274AS-H-100M=P3" DEM10050C 65,41.5 r0 top locked
L6 "1274AS-H-100M=P3" DEM10050C 67.5,30.5 r0 top locked
L7 "1274AS-H-100M=P3" DEM10050C 65,8.5 r0 top
L8 "1274AS-H-100M=P3" DEM10050C 67.5,19.5 r0 top
Logo1 "Texas Instruments" TI_Stacked_Overlay_Small 16.25,66.25 r0 top
Logo2 "CE Mark" CE_Mark_5mm 49.25,110.5 r0 top
Logo3 "FCC disclaimer" FCC_disclaimer_stacked 45,116.5 r0 top
Logo4 "WEEE logo" WEEE_Minimum 41.25,111.25 r0 top
R1 "" 0402L 46.25,99.75 r180 top
R2 "ERA-2AEB102X" 0402L 46.25,29.75 r180 top
R3 "RMCF0402FT10K0" 0402L 46.25,28 r180 top
R4 "RMCF0402FT10K0" 0402L 46.25,27.125 r180 top
R5 "RMCF0402FT10K0" 0402L 46.25,26.25 r180 top
R6 "RMCF0402FT10K0" 0402L 51,20.75 r270 top
R7 "ERJ-2RKF4700X" 0402L 35,66.25 r90 bottom
R8 "RMCF0402FT10K0" 0402L 6.604,53.974 r270 top
R9 "DNP" 0402L 16,56.5 r270 top
R10 "RMCF0402FT10K0" 0402L 17.297,56.514 r270 top
R11 "RC0402FR-072K2L" 0402L 23.426,54.482 r0 top
R12 "RC0402FR-072K2L" 0402L 23.426,52.232 r0 top
R13 "ERJ-3GEY0R00V" 0603L 20.279,54.482 r180 top
R14 "ERJ-3GEY0R00V" 0603L 20.279,52.232 r180 top
R15 "RC0402FR-0749R9L" 0402L 32.537,46.99 r180 bottom
R16 "RMCF0402FT10K0" 0402L 32.512,48.514 r180 bottom
R17 "DNP" 0402L 46.25,98.875 r180 top
R18 "RC0402FR-0749R9L" 0402L 29.235,50.876 r180 bottom
R19 "RMCF0402FT10K0" 0402L 33.02,52.283 r270 bottom
R20 "RMCF0402FT10K0" 0402L 46.25,98 r180 top
R21 "RMCF0402FT10K0" 0402L 46.25,97.125 r180 top
R22 "RMCF0402FT10K0" 0402L 46.25,96.25 r180 top
R23 "RMCF0402FT10K0" 0402L 51,90.75 r270 top
R24 "DNP" 0402L 46.25,28.875 r180 top
SH-J1 "SNT-100-BK-G" SNT-100-BK-G 47.5,67.5 r90 top
SH-J2 "SNT-100-BK-G" SNT-100-BK-G 47.5,52.5 r90 top
TP1 "3.3V" Keystone5000 35,68.75 r90 top
TP2 "GND" Keystone5001 37.5,8.75 r90 top
TP3 "GND" Keystone5001 30,100 r90 top
TP4 "FAULT1z" Keystone5003 30,92.5 r90 top
TP5 "FAULT2z" Keystone5003 30,32.5 r90 top
TP6 "SCL" Keystone5003 20,45.5 r0 top
TP7 "SDA" Keystone5003 30,37.5 r0 top
TP8 "WARN1z" Keystone5003 30,82.5 r90 top
TP9 "WARN2z" Keystone5003 30,22.5 r90 top
TP10 "SDIN1" Keystone5003 20,70.5 r90 top
TP11 "LRCLK" Keystone5003 20,83 r90 top
TP12 "SCLK" Keystone5003 20,76.75 r90 top
TP13 "SDOUT" Keystone5003 20,60.5 r90 top
TP14 "MUTE1z" Keystone5003 30,87.5 r90 top
TP15 "MUTE2z" Keystone5003 30,27.5 r90 top
TP16 "SDIN2" Keystone5003 30,17.5 r90 top
TP17 "PDN2z" Keystone5003 30,12.5 r90 top
TP18 "PDN1z" Keystone5003 30,77.5 r90 top
U1 "TAS5825MRHBR" RHB0032N 55,95 r270 top locked
U2 "TAS5825MRHBR" RHB0032N 55,25 r270 top locked
U3 "24LC512-I/ST" TSSOP-8 11.125,54.75 r0 top
U4 "LVC2G157" DCU0008A_N 36,52 r180 bottom
U5 "LVC2G157" DCU0008A_N 36,48 r180 bottom
ZZ1 "These assemblies are ESD sensitive, ESD precautions shall be observed." AssemblyNote 3,129 r0 top
ZZ2 "These assemblies must be clean and free from flux and all contaminants. Use of no clean flux is not acceptable." AssemblyNote 3,126 r0 top
ZZ3 "These assemblies must comply with workmanship standards IPC-A-610 Class 2, unless otherwise specified." AssemblyNote 3,123 r0 top

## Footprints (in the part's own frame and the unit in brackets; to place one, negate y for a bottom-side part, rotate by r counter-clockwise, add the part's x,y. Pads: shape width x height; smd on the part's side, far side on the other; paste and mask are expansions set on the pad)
0402L [mm] "0402 from SM-752 data"
  rect 0.6x0.5 smd: 1(-0.5,0) 2(0.5,0)
0603L [mm] "0603 from SM-752 data"
  rect 0.8x0.85 smd: 1(-0.7,0) 2(0.7,0)
  silkscreen extent -0.07,-0.33 0.07,0.33
0805_KTR [mm] "ROHM"
  rect 0.7x1.15 smd: 1(-0.95,0) 2(0.95,0)
  silkscreen extent -0.35,-0.7 0.35,0.7
AssemblyNote [mm] "Assembly Note"
CE_Mark_5mm [mm] "Minimum text height for CE Mark"
CONN_QTS-050-01-F-D-A [mil] "SAMTEC"
  rect 16x57 smd: 1(-693.75,121.5) 2(-693.75,-121.5) 3(-668.75,121.5) 4(-668.75,-121.5) 5(-643.75,121.5) 6(-643.75,-121.5) 7(-618.75,121.5) 8(-618.75,-121.5) 9(-593.75,121.5) 10(-593.75,-121.5) 11(-568.75,121.5) 12(-568.75,-121.5) 13(-543.75,121.5) 14(-543.75,-121.5) 15(-518.75,121.5) 16(-518.75,-121.5) 17(-493.75,121.5) 18(-493.75,-121.5) 19(-468.75,121.5) 20(-468.75,-121.5) 21(-443.75,121.5) 22(-443.75,-121.5) 23(-418.75,121.5) 24(-418.75,-121.5) 25(-393.75,121.5) 26(-393.75,-121.5) 27(-368.75,121.5) 28(-368.75,-121.5) 29(-343.75,121.5) 30(-343.75,-121.5) 31(-318.75,121.5) 32(-318.75,-121.5) 33(-293.75,121.5) 34(-293.75,-121.5) 35(-268.75,121.5) 36(-268.75,-121.5) 37(-243.75,121.5) 38(-243.75,-121.5) 39(-218.75,121.5) 40(-218.75,-121.5) 41(-193.75,121.5) 42(-193.75,-121.5) 43(-168.75,121.5) 44(-168.75,-121.5) 45(-143.75,121.5) 46(-143.75,-121.5) 47(-118.75,121.5) 48(-118.75,-121.5) 49(-93.75,121.5) 50(-93.75,-121.5) 51(93.75,121.5) 52(93.75,-121.5) 53(118.75,121.5) 54(118.75,-121.5) 55(143.75,121.5) 56(143.75,-121.5) 57(168.75,121.5) 58(168.75,-121.5) 59(193.75,121.5) 60(193.75,-121.5) 61(218.75,121.5) 62(218.75,-121.5) 63(243.75,121.5) 64(243.75,-121.5) 65(268.75,121.5) 66(268.75,-121.5) 67(293.75,121.5) 68(293.75,-121.5) 69(318.75,121.5) 70(318.75,-121.5) 71(343.75,121.5) 72(343.75,-121.5) 73(368.75,121.5) 74(368.75,-121.5) 75(393.75,121.5) 76(393.75,-121.5) 77(418.75,121.5) 78(418.75,-121.5) 79(443.75,121.5) 80(443.75,-121.5) 81(468.75,121.5) 82(468.75,-121.5) 83(493.75,121.5) 84(493.75,-121.5) 85(518.75,121.5) 86(518.75,-121.5) 87(543.75,121.5) 88(543.75,-121.5) 89(568.75,121.5) 90(568.75,-121.5) 91(593.75,121.5) 92(593.75,-121.5) 93(618.75,121.5) 94(618.75,-121.5) 95(643.75,121.5) 96(643.75,-121.5) 97(668.75,121.5) 98(668.75,-121.5) 99(693.75,121.5) 100(693.75,-121.5)
  rect 100x25 smd: 101(-726,0) 104(-61.25,0) 105(61.25,0) 108(726.25,0)
  rect 185x25 smd: 102(-518.75,0) 103(-268.75,0) 106(269,0) 107(518.75,0)
  round 39 hole 40 unplated: MH1(-757.5,80) MH2(757.5,80)
  silkscreen extent -788,-117 787,118
DCU0008A_N [mm] "TSSOP, 8-Leads, Body 2x2.3mm, Pitch 0.5mm, IPC Medium Density"
  oval 0.8x0.3 smd: 1(-1.6,0.75) 2(-1.6,0.25) 3(-1.6,-0.25) 4(-1.6,-0.75) 5(1.6,-0.75) 6(1.6,-0.25) 7(1.6,0.25) 8(1.6,0.75)
  silkscreen extent -1.05,-1.05 0.38,1.05
DEM10050C [mm] "MuRata inductor"
  rrect5% 2.15x5 smd: 1(-4.175,0) 2(4.175,0)
FCC_disclaimer_stacked [mm]
Fiducial6.4-20 [mm]
  round 0.635 smd mask+0: 1(0,0)
  Top Layer keep-out circle w1.178: c0,0 r0.5
Harwin_R30-1003002 [mm] "Standoff Hex Brass M3"
HARWIN_S1911-46R [mm] "HARWIN"
  rect 2.48x3 smd mask+0: 1(-2.69,0) 2(2.69,0)
  silkscreen extent -0.5,-1.5 0.5,1.5
JST_B2PS-VH [mm] "JST Sales America Inc"
  rect 2.4x2.4 hole 1.778: 1(0,1.98)
  round 2.4 hole 1.778: 2(0,-1.98)
  silkscreen extent 2,-3.93 14.9,3.93
Keystone5000 [mil] "For Keystone 500x miniature loop terminals"
  round 80 hole 40: 1(0,0)
  silkscreen extent -52,-52 52,52
Keystone5001 [mil] "For Keystone 500x miniature loop terminals"
  round 80 hole 40: 1(0,0)
  silkscreen extent -52,-52 52,52
Keystone5003 [mil] "For Keystone 500x miniature loop terminals"
  round 80 hole 40: 1(0,0)
  silkscreen extent -52,-52 52,52
Keystone_7006 [mm] "KEYSTONE"
  round 8.5 hole 3.658: 1(0,0)
  silkscreen extent -4.8,-4.8 4.8,4.8
Keystone_7007 [mm] "KEYSTONE"
  round 8.5 hole 3.658: 1(0,0)
  silkscreen extent -4.8,-4.8 4.8,4.8
LTST-C170KGKT_Green [mm] "LITE-ON"
  rect 1.2x1.2 smd: 1(-1.05,0) 2(1.05,0)
  silkscreen extent -1.6,-0.9 2.1,0.9
RHB0032N [mm] "QFN, 32-Leads, Body 5x5mm, Pitch 0.5mm, Thermal Pad 3.45x3.45mm"
  rrect40% 0.6x0.25 smd: 1(-2.4,1.75) 2(-2.4,1.25) 3(-2.4,0.75) 4(-2.4,0.25) 5(-2.4,-0.25) 6(-2.4,-0.75) 7(-2.4,-1.25) 8(-2.4,-1.75) 17(2.4,-1.75) 18(2.4,-1.25) 19(2.4,-0.75) 20(2.4,-0.25) 21(2.4,0.25) 22(2.4,0.75) 23(2.4,1.25) 24(2.4,1.75)
  rrect40% 0.25x0.6 smd: 9(-1.75,-2.4) 10(-1.25,-2.4) 11(-0.75,-2.4) 12(-0.25,-2.4) 13(0.25,-2.4) 14(0.75,-2.4) 15(1.25,-2.4) 16(1.75,-2.4) 25(1.75,2.4) 26(1.25,2.4) 27(0.75,2.4) 28(0.25,2.4) 29(-0.25,2.4) 30(-0.75,2.4) 31(-1.25,2.4) 32(-1.75,2.4)
  rrect3% 3.45x3.45 smd paste-1.725: 33(0,0)
  rrect7% 1.49x1.49 on Top Paste: ""(-0.845,0.845) ""(-0.845,-0.845) ""(0.845,0.845) ""(0.845,-0.845)
  silkscreen extent -2.72,-2.73 2.72,2.73
SM_RADIAL_10BMM [mm] "Nichicon 10x10"
  rect 4x2.5 smd: 1(-4,0) 2(4,0)
  silkscreen extent -5.25,-5.25 5.25,5.25
SNT-100-BK-G [mil] "Samtec STEP model"
  round 1 on Mech3: 0(0,0)
Sullins_PBC02SAAN [mm] "Sullins 100mil, 1x2, 230 mil above insulator"
  rect 1.65x1.65 hole 1.016: 1(0,1.27)
  round 1.65 hole 1.016: 2(0,-1.27)
  silkscreen extent -1.37,-2.54 1.27,3.1
TI_Stacked_Overlay_Small [mm]
TSSOP-8 [mm] "TSSOP, 8-Leads, Body 3.1x4.5mm (max), Pitch 0.65mm, IPC Medium Density"
  rrect50% 1.7x0.35 smd: 1(-2.85,0.975) 2(-2.85,0.325) 3(-2.85,-0.325) 4(-2.85,-0.975) 5(2.85,-0.975) 6(2.85,-0.325) 7(2.85,0.325) 8(2.85,0.975)
  silkscreen extent -2.97,-1.55 1.6,1.82
WEEE_Minimum [mm] "WEEElie bin"
  silkscreen extent 0.56,-1.79 1.38,1.88

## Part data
C1 C7 C8 C11 C12 C16 C19 C35 C45: library part CMP-0006297-2, "CAP, CERM, 0.1 uF, 50 V, +/- 10%, X7R, 0402"
C2 C17 C20 C36 C37 C38 C39 C40: library part CMP-0007821-1, "CAP, CERM, 22 uF, 35 V, +/- 20%, JB, 0805"
C3 C21: library part CMP-0006949-5, "CAP, CERM, 4.7 uF, 10 V, +/- 10%, X5R, 0603"
C4 C22: library part CMP-0006860-5, "CAP, CERM, 0.1 uF, 16 V, +/- 10%, X7R, 0603"
C5 C14 C15 C23 C32 C33: library part CMP-0006868-5, "CAP, CERM, 1 uF, 16 V, +/- 10%, X5R, 0603"
C6 C9 C10 C13 C24 C27 C28 C30: library part CMP-0007047-4, "CAP, CERM, 0.22 uF, 50 V, +/- 10%, X7R, 0603"
C18 C34: library part CMP-0011092-1, "CAP, AL, 390 uF, 35 V, +/- 20%, 0.08 ohm, SMD"
C25 C26 C29 C31 C41 C42 C43 C44: library part CMP-0007814-2, "CAP, CERM, 0.68 uF, 50 V, +/- 10%, X7R, 0805"
D1: library part CMP-0002888-1, "LED, Green, SMD"
FID1 FID2 FID3 FID4 FID5 FID6: library part CMP-0077181-1, "Fiducial mark.  There is nothing to buy or mount."
H9 H10 H11 H12: library part CMP-0003674-1, "Standoff, HexBrass M3, 30 mm"
J1 J10: library part CMP-0075020-1, "JUMPER TIN SMD"
J2 J3: library part CMP-0054566-1, "Header, 100mil, 2x1, Gold, TH"
J4 J8 J9 J11: library part CMP-0074989-1, "Header (friction lock), 3.96mm, 2x1, Tin, R/A, TH"
J5: library part CMP-0055971-1, "Connector, 100 Pos. 0.635mm, SMT"
J6: library part CMP-0055127-1, "Binding Post, RED, TH"
J7: library part CMP-0055128-1, "Binding Post, BLACK, TH"
L1 L2 L3 L4 L5 L6 L7 L8: library part CMP-0077807-1, "Inductor, Shielded, Ferrite, 10 µH, 4.4 A, 0.0304 ohm, SMD"
Logo1: library part CMP-0074838-1, "Texas Instrument Corporate Signature"
Logo2: library part CMP-0074844-1
Logo3: library part CMP-0074847-1, "FCC_disclaimer"
Logo4: library part CMP-0074769-1
R1 R17 R24: library part CMP-0026992-2, "RES, 0, 5%, 0.063 W, 0402"
R2: library part CMP-0026770-1, "RES, 1.00 k, 0.1%, 0.063 W, 0402"
R3 R4 R5 R6 R8 R9 R10 R16 R19 R20 R21 R22 R23: library part CMP-0026754-1, "RES, 10.0 k, 1%, 0.063 W, AEC-Q200 Grade 0, 0402"
R7: library part CMP-0026699-1, "RES, 470, 1%, 0.1 W, AEC-Q200 Grade 0, 0402"
R11 R12: library part CMP-0026729-1, "RES, 2.20 k, 1%, 0.063 W, 0402"
R13 R14: library part CMP-0025874-3, "RES, 0, 5%, 0.1 W, 0603"
R15 R18: library part CMP-0026738-1, "RES, 49.9, 1%, 0.063 W, 0402"
SH-J1 SH-J2: library part CMP-0003623-1, "Shunt, 100mil, Gold plated, Black"
TP1: library part CMP-0055137-1, "Test Point, Miniature, Red, TH"
TP2 TP3: library part CMP-0055138-1, "Test Point, Miniature, Black, TH"
TP4 TP5 TP6 TP7 TP8 TP9 TP10 TP11 TP12 TP13 TP14 TP15 TP16 TP17 TP18: library part CMP-0055140-1, "Test Point, Miniature, Orange, TH"
U1 U2: library part CMP-0077820-2, "4.5 V to 26.4 V, Inductor-Less, Digital Input, Stereo, Closed-Loop Class-D Audio Amplifier with 96-kHz/192-kHz Extended Audio Processing, RHB0032N (VQFN-32)"
U3: library part CMP-0005242-2, "EEPROM, 512KBIT, 400KHZ, 8TSSOP"
U4 U5: library part CMP-0051026-1, "Single 2-Line to 1-Line Data Selector/Multiplexer, DCU0008A, LARGE T&R"
ZZ1: library part CMP-0077236-1
ZZ2: library part CMP-0077237-1
ZZ3: library part CMP-0077238-1

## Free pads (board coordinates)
  round 7 hole 3.25: 0(9,35) 0(9,85)

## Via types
v1: diameter 0.508, hole 0.254, Top Layer to Bottom Layer, tented both sides, 343 vias
v2: diameter 0.635, hole 0.254, Top Layer to Bottom Layer, tented both sides, 130 vias
v3: diameter 0.508, hole 0.254, Top Layer to Bottom Layer, 14 vias
v4: diameter 0.5, hole 0.2, Top Layer to Bottom Layer, 10 vias
v5: diameter 0.762, hole 0.254, Top Layer to Bottom Layer, tented both sides, 8 vias
v6: diameter 6.5, hole 3.25, Top Layer to Bottom Layer, tented both sides, 4 vias

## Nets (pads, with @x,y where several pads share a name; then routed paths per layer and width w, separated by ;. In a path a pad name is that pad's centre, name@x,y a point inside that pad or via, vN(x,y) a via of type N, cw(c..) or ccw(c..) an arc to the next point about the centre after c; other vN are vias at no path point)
+3.3V: C7.1 C8.2 C11.2 C12.2 C45.2 J2.1 J3.1 J5.58 J5.60 J5.62 J5.64 R7.2 R8.2 R9.1 R11.2 R12.2 R19.1 TP1.1 U3.8 U4.8 U5.8 | length 114.1
  Top Layer w0.25: C7.1@13.962,57.784 14.062,57.884 v5(14.062,58.53)
  Top Layer w0.254: R8.2@6.604,53.474 6.604,52.375 6.979,52 v2(10.625,52) ; C7.1@13.962,57.784 13.975,57.771 13.975,56.5 ; U3.8@13.975,55.725 13.975,56.5 ; R9.1@16,57 15.5,57 15,56.5 13.975,56.5 ; R12.2@23.926,52.232 v5(24.926,52.232) ; R11.2@23.926,54.482 v5(25.02,54.482)
  Top Layer w0.5: v2(17.5,61.25) 17.5,63.75 v2(18.75,65) ; TP1.1@35,68.75 37.52,66.23 J2.1@47.5,66.23
  Signal Layer 2 w0.5: 14,54.75 14.062,54.812 v5(14.062,58.53) ; v5(24.926,52.232) 24.926,53.301 25.02,53.395 v5(25.02,54.482) ; v1(33.625,49.75) 34.375,50.5 34.375,51.75 v2(34.375,53.5) ; J3.1@47.5,53.77 J2.1@47.5,66.23
  Signal Layer 2 w0.75: 10.5,54.75 21.25,54.75 22.625,53.375 31.5,53.375 33.125,51.75 34.375,51.75
  Bottom Layer w0.2: R19.1@33.02,52.783 33.053,52.75 U4.8@34.5,52.75 ; U4.8@34.375,52.875 v2(34.375,53.5) ; v2@34.4,53.5 34.4,54.204 C8.2@34.552,54.356
  Bottom Layer w0.25: v1(33.625,49.75) C11.2@34.5,49.75 U5.8@34.5,48.75
  Bottom Layer w0.254: v2(10.625,52) 10.625,53.677 v2(10.922,53.974) ; R7.2@35,66.75 TP1.1@35,68.75
  Bottom Layer w0.5: 13.75,54.875 16.125,54.875 17.5,56.25 v2(17.5,61.25) ; v2(18.75,65) 27.5,65 31.25,68.75 TP1.1@35,68.75
  other v2: 10.875,55.5
  other v5: 10.086,54.339 10.086,55.214
\FAULT1: J5.22 R20.1 TP4.1 U1.9 | length 61.2
  Top Layer w0.2: v2(26.5,77.5) v2(26.5,81.25) ; R20.1@46.75,98 v2(47.625,98) 48.875,96.75 U1.9@52.6,96.75
  Bottom Layer w0.2: J5.22@12.086,71.271 15.771,71.271 19,74.5 26,74.5 26.5,75 v2(26.5,77.5) ; v2(26.5,81.25) 26.5,89 TP4.1@30,92.5 36.25,92.5 41.75,98 v2(47.625,98)
\FAULT2: J5.24 R3.1 TP5.1 U2.9 | length 91.7
  Top Layer w0.2: v2(13.75,70) 6.314,70 4.064,67.75 4.064,48.936 9.986,43.014 12.486,43.014 15,40.5 v2(25,40.5) ; R3.1@46.75,28 v2(47.625,28) 48.875,26.75 U2.9@52.6,26.75
  Bottom Layer w0.2: J5.24@12.086,70.636 13.114,70.636 v2(13.75,70) ; v2(25,40.5) 26.25,39.25 26.25,36.25 TP5.1@30,32.5 38.75,32.5 43.25,28 v2(47.625,28)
